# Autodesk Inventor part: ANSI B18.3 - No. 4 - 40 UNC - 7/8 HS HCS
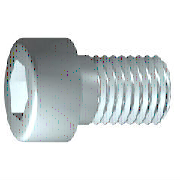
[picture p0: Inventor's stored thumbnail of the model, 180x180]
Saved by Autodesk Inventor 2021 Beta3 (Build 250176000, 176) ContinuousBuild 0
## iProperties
IsCustomPart: 0
Created: 2012-02
Part Number: ANSI B18.3 - No. 4 - 40 UNC - 7/8 HS HCS
Material: Generic
Description: Hexagon Socket Head Cap Screw
Document SubType Name: Modeling
Standard: ANSI B18.3
Designer: John
Standard Revision: 2003
Standards Organization: ANSI
Language: en-US
Size Designation: No. 4 - 40 UNC - 7/8
Categories: <MemberInstance><Categories><Category DisplayName="Fasteners" InternalName="e4da775c-781d-43d5-af7c-5136215cf5a6" Mnemonic="FSTN"><Category DisplayName="Bolts"
Density: 1 g/cm^3
Appearance: Default
Author: John
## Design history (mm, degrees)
sketch "Sketch1"
  geometry: L1 (-0.754, 0)-(22.225, 0); L2 (22.225, 0)-(22.225, 1.422); L3 (22.225, 1.422)-(1.588, 1.422); L4 (1.588, 1.422)-(0, 1.422); L5 (0, 1.422)-(0, 1.422); L6 (0, 1.422)-(0, 2.324); L7 (0, 2.324)-(-2.845, 2.324); L8 (-2.845, 2.324)-(-2.845, 1.378); L9 (-2.845, 1.378)-(-1.549, 1.378); L10 (-1.549, 1.378)-(-0.754, 0); L11 (-7.859, 0)-(27.239, 0) reference; L12 (0, -0.465)-(0, 2.789) reference; L13 (1.588, 1.422)-(0, 1.422)
  constraints: 22 end point, 6 parallel, 2 collinear, 2 perpendicular, 1 horizontal, 1 point on line
  dimensions: "d1" = 20.6373 distance from line of L3.end L2 (= GEL); "d2" = 1.5876 distance of L4.end L3.end (computed from GAL); "d3" = 2.8448 distance between parallel lines of L8 L6 (= KOH); "d4" = 1.2954 distance of L8.end L9.end (= INTI); "d5" = 60 deg angle of L10 L1; "d6" = 2.8448 diameter of L3 L1 (= GD); "d7" = 2.8448 diameter of L5 L1 (= BDM); "d8" = 2.75696 diameter of L9 L1 (= 1.1547 x SW); "d9" = 4.6482 diameter of L7 L1 (= KOD); "d26" = 22.225 distance between parallel lines of L12 L2 (= NLG)
revolve "Body" sketch "Sketch1" stored, may be unused: angle "d10" = 90 deg
sketch "Sketch2"
  geometry: L1 (0, -3.254)-(0, 3.254) reference; L2 (-3.254, 0)-(3.254, 0) reference; L3 (1.378, 0)-(0.689, -1.194); L4 (0.689, -1.194)-(-0.689, -1.194); L5 (-0.689, -1.194)-(-1.378, 0); L6 (-1.378, 0)-(-0.689, 1.194); L7 (-0.689, 1.194)-(0.689, 1.194); L8 (0.689, 1.194)-(1.378, 0); 2 further points
  constraints: 12 end point, 1 coincident, 1 horizontal alignment, 1 point on line, 12 other
extrude "Slot" join sketch "Sketch2" stored distance "d11" = 10; taper "d12" = 0 deg
workplane "Work Plane1"
fillet "Fillet2" dims "d30" = 0.1016 (= R)
body "Solid1"
fillet "Fillet1" dims "d17" = 0.2286 (= RR)
feature "Thread" dims "d13" = 20.6373 (= GEL), "d14" = 0
chamfer "Chamfer1" distance "d15" = 0.37846 (= -0.5 x SPD + 0.5 x GD); stored, may be unused: second distance "d16" = 0.37846 (= GUL), angle "d27" = 45 deg
other parameters: "GD" = 2.8448 [user parameter; used in 2 equation terms], "NLG" = 22.225 [user parameter; used in 1 equation term], "GEL" = 20.6373 [user parameter; used in 2 equation terms], "KOD" = 4.6482 [user parameter; used in 1 equation term], "KOH" = 2.8448 [user parameter; used in 1 equation term], "INTI" = 1.2954 [user parameter; used in 1 equation term], "GAL" = 1.5875 [user parameter; used in 1 equation term], "GUL" = 0.37846 [user parameter; used in 1 equation term], "BDM" = 2.8448 [user parameter; used in 1 equation term], "SW" = 2.3876 [user parameter; used in 2 equation terms], "RR" = 0.2286 [user parameter; used in 1 equation term], "SPD" = 2.08788 [user parameter; used in 2 equation terms], "d19" = 0, "d28" = 0, "d29" = 0, "R" = 0.1016 [user parameter; used in 1 equation term], "PHH" = 0.127 [user parameter], "GD1" = 2.08788 (= SPD) [user parameter], "THREADDIA" = 2.8448 [user parameter], "FAWI" = 45 deg [user parameter], "PTC" = 0.635 (computed from TPU) [user parameter], "KOH1" = 2.5654 [user parameter], "NND" = 2.8448 [user parameter], "TOA" = 30 deg [user parameter], "E0" = 2.75768 (= 1.155 x SW) [user parameter]
